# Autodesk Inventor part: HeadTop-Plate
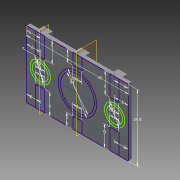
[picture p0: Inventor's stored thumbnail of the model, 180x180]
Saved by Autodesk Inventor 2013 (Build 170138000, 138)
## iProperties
Created: 2013-04
Part Number: HeadTop-Plate
Material: Generic
Document SubType Name: Modeling
Designer: frankenteddy
Density: 1 g/cm^3
Author: frankenteddy
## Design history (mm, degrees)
sketch "Sketch1"
  geometry: L1 (-22.5, 14.75)-(22.5, 14.75); L2 (22.5, 14.75)-(22.5, -14.75); L3 (22.5, -14.75)-(-22.5, -14.75); L4 (-22.5, -14.75)-(-22.5, 14.75); L5 (-18.5, 14.75)-(-14.5, 14.75); L6 (-14.5, 14.75)-(-14.5, 5.75); L7 (-14.5, 5.75)-(-18.5, 5.75); L8 (-18.5, 5.75)-(-18.5, 14.75); L9 (-2, 14.75)-(2, 14.75); L10 (2, 14.75)-(2, 9.75); L11 (2, 9.75)-(-2, 9.75); L12 (-2, 9.75)-(-2, 14.75); L13 (14.5, 14.75)-(18.5, 14.75); L14 (18.5, 14.75)-(18.5, 5.75); L15 (18.5, 5.75)-(14.5, 5.75); L16 (14.5, 5.75)-(14.5, 14.75); L17 (-18.5, -14.75)-(-14.5, -14.75); L18 (-14.5, -14.75)-(-14.5, -5.75); L19 (-14.5, -5.75)-(-18.5, -5.75); L20 (-18.5, -5.75)-(-18.5, -14.75); L21 (-2, -14.75)-(2, -14.75); L22 (2, -14.75)-(2, -9.75); L23 (2, -9.75)-(-2, -9.75); L24 (-2, -9.75)-(-2, -14.75); L25 (14.5, -14.75)-(18.5, -14.75); L26 (18.5, -14.75)-(18.5, -5.75); L27 (18.5, -5.75)-(14.5, -5.75); L28 (14.5, -5.75)-(14.5, -14.75); L29 (-16.5, 5.75)-(-16.5, 14.75); L30 (0, 9.75)-(0, 14.75); L31 (16.5, 5.75)-(16.5, 14.75); L32 (16.5, -5.75)-(16.5, -14.75); L33 (0, -9.75)-(0, -14.75); L34 (-16.5, -5.75)-(-16.5, -14.75); L35 (-22.5, 0)-(22.5, 0); L36 (0, 14.75)-(0, -14.75); C1 r 7.5 at (0, 0); C2 r 3.5 at (16.5, 0); C3 r 3.5 at (-16.5, 0); C4 r 4.5 at (-16.5, 0); C5 r 8.5 at (0, 0); C6 r 4.5 at (16.5, 0); 4 further points
  constraints: 72 end point, 16 midpoint, 14 parallel, 9 perpendicular, 7 coincident, 7 horizontal, 6 centre point, 6 point on line, 2 collinear, 1 horizontal alignment, 1 vertical alignment
  dimensions: "d0" = 45 distance of L1.start L1.end; "d2" = 29.5 distance of L3.end L1.start; "d3" = 15 diameter of C1; "d4" = 7 diameter of C2; "d5" = 7 diameter of C3; "d6" = 6 distance from line of C3.centre L4; "d7" = 6 distance from line of C2.centre L2; "d8" = 4 distance of L6.end L7.end; "d9" = 4 distance of L10.end L11.end; "d10" = 4 distance of L14.end L15.end; "d11" = 4 distance of L19.end L18.end; "d12" = 4 distance of L23.end L22.end; "d13" = 4 distance of L27.end L26.end; "d14" = 6 distance between parallel lines of L4 L29; "d15" = 6 distance between parallel lines of L4 L34; "d16" = 6 distance between parallel lines of L2 L32; "d17" = 6 distance between parallel lines of L2 L31; "d18" = 9 distance of L5.end L6.end; "d19" = 9 distance of L17.end L18.end; "d20" = 5 distance of L9.end L10.end; "d21" = 5 distance of L21.end L22.end; "d22" = 9 distance of L15.end L13.start; "d23" = 9 distance of L27.end L25.start; "d40" = 9 diameter of C4; "d41" = 17 diameter of C5; "d42" = 9 diameter of C6
extrude "Extrusion1" new body sketch "Sketch1" distance "d24" = 1.62; taper "d25" = 0 deg
extrude "Extrusion2" join sketch "Sketch1" distance "d26" = 3.62; taper "d27" = 0 deg
workplane "Work Plane1"
sketch "Sketch2"
  geometry: L1 (0, 0)-(1.62, 0) reference; L2 (1.62, 0)-(1.62, -29.5) reference; L3 (1.62, -29.5)-(0, -29.5); L4 (0, -29.5)-(0, 0); L5 (1.62, -14.75)-(0, -14.75); L6 (1.62, -14.75)-(4.62, -14.75); L7 (4.62, -14.75)-(4.62, -11.25); L8 (4.62, -11.25)-(1.62, -11.25); L9 (1.62, -11.25)-(1.62, -14.75); L10 (8.12, -14.75)-(1.12, -14.75); A1 r 3.5 centre (4.62, -14.75) between (8.12, -14.75) and (1.12, -14.75)
  constraints: 20 end point, 4 parallel, 3 horizontal, 2 perpendicular, 2 point on circle, 2 point on line, 1 centre point, 1 coincident, 1 midpoint, 1 vertical
  dimensions: "d28" = 1.62 distance of L2.end L3.end; "d29" = 29.5 distance of L1.end L2.end; "d30" = 3 distance of L8.end L7.end; "d31" = 3.5 distance of L7.end L6.end; "d32" = 7 diameter of A1
revolve "Revolution1" sketch "Sketch2" stored, may be unused: angle "d33" = 90 deg
workplane "Work Plane2"
sketch "Sketch3"
  geometry: L1 (0, 0)-(1.62, 0) reference; L2 (1.62, 0)-(1.62, -29.5) reference; L3 (1.62, -29.5)-(0, -29.5); L4 (0, -29.5)-(0, 0); L5 (1.62, -14.75)-(0, -14.75); L6 (1.62, -14.75)-(4.62, -14.75); L7 (4.62, -14.75)-(4.62, -7.25); L8 (4.62, -7.25)-(1.62, -7.25); L9 (1.62, -7.25)-(1.62, -14.75); L10 (12.12, -14.75)-(0, -14.75); L11 (0, -14.75)-(0, -20.658); A1 r 7.5 centre (4.62, -14.75) between (0, -20.658) and (0, -8.842)
  constraints: 22 end point, 4 parallel, 3 horizontal, 3 perpendicular, 3 point on circle, 2 midpoint, 2 point on line, 1 centre point, 1 coincident, 1 collinear, 1 vertical
  dimensions: "d34" = 1.62 distance of L2.end L3.end; "d35" = 29.5 distance of L1.end L2.end; "d36" = 3 distance of L8.end L7.end; "d37" = 7.5 distance of L7.end L6.end; "d38" = 15 diameter of A1
revolve "Revolution2" sketch "Sketch3" stored, may be unused: angle "d39" = 90 deg
mirror "Mirror1"
extrude "Extrusion3" join sketch "Sketch1" distance "d43" = 3.12; taper "d44" = 0 deg
body "Solid1"
